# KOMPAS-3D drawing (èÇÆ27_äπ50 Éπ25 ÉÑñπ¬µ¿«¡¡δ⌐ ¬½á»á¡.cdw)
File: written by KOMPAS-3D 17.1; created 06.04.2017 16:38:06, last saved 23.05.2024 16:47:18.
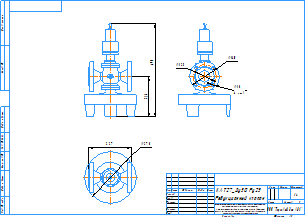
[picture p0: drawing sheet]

Sheet 1: A3, landscape

Title block, sheet 1: name: КАТ27_Ду50 Ру25 / Редукционный клапан; material: Сталь 20  ГОСТ 1050-88; sheets: 1; sheet format: A3; stored path: C:\Users\kka\KOMPAS_Work\!Trash\Редукционный клапан GP-2000\KOMPAS 2D\GP-2000 _ Ду40 Ру25 Редукционный клапан.cdw

Views: Спереди 1, Спереди, Проекционный вид 2, Проекционный вид 3
Referenced files in C:\Users\klav\Desktop\Модели\КАТ27\KOMPAS 3D\: КАТ27_ Ду50 Ру25 Редукционный клапан.m3d
Referenced files in C:\Users\klav\Desktop\Модели\КАТ 27\KOMPAS 3D\: КАТ27_ Ду50 Ру25 Редукционный клапан.m3d
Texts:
  Klimkovich
  ADL
  Рама для чертежей
  Лит-Масса-Масштаб
  Материал-Предприятие
  Масштаб
  Изм.
  Лист
  № докум.
  Подп.
  Дата
  Лит.
  Разраб.
  Пров.
  Т.контр.
  Листов
  Внимание! Данный продукт является объектом авторского права ООО «Торговый Дом АДЛ».
  Запрещается изменение, копирование, распространение
  (в том числе путем копирования на другие сайты и ресурсы в Интернете)
  или любое иное использование информации и объектов без предварительного
  согласия правообладателя (ООО «Торговый Дом АДЛ»).
  Н.контр.
  Утв.
  ООО "Торговый дом АДЛ"
  Изменение
  Номер документа
  Подпись
  Обозначение документа
  Наименование изделия
  Масса изделия по ГОСТ 2.109-73
  Порядковый номер листа
  Общее количество листов в документе
  Характер работы, выполненной лицом, подписавшим документ
  Наименование или индекс предприятия, выпускающего документ
  Инв. № подл.
  Подп. и дата
  Взам. инв. №
  Инв. № дубл.
  Инвентарный номер подлинника по ГОСТ 2.501-68
  Подпись принявшего подлинник в отдел технической документации
  Инвентарный номер подлинника, взамен которого выпущен данный подлинник
  Инвентарный номер дубликата по ГОСТ 2.502-68
  Подпись принявшего дубликат в отдел технической документации
  Справ. №
  Перв. примен.
  Обозначение документа, взамен или на основании которого выпущен данный документ
  Обозначение документа, в котором впервые записан данный документ
  Подпись лица, копировавшего чертеж
  Обозначение формата листа
  !Рама для чертежа
Dimensions and other numbers on the sheet: 216; 498; 278; 227; 160; 18; 4 отв.; 125; 1:4; 1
